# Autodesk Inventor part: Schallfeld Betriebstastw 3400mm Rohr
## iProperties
Shininess: 20.0
Length Units: 11269
Angle Units: 11279
Time Units: 11290
Mass Units: 11283
Length Display Precision: 2
Angle Display Precision: 2
Part Number: Schallfeld Betriebstastw 3400mm Rohr
Material: Lexan (klar)
Document SubType Name: Modellieren
Description: Schallfeld 3,4m
Checked By: Alves
Created: 2005-08
Designer: Ohle
Manufacturer: Standard
Standards Organization: Custom
Density: 0.0
Volumn: 0.0
Area: 0.0
PropertySet Name: Model Information
Control State: 0
Master: False
Checked Out: False
Last Check In By: Kramp
Last Check In Date: 2005-08-11
ME: ST
Title: Schallfelder
Author: Ohle
Comments: keine Bemerkung
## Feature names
1. Innenglocke [Revolution]
